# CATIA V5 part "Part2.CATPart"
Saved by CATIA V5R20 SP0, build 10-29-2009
Part number: Part2
Bounding box of the stored display mesh (mm): x -1.857 to 1.857, y -0.35 to 0.35, z -1.857 to 1.857
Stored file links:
  C:\Users\scupi\Desktop\Product\Part2.CATPart
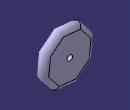
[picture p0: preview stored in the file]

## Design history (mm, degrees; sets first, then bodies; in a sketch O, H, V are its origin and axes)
Body1 (main body)
  Sketch1 on yz-plane, origin (0, 0, 0), H (0, 1, 0), V (0, 0, 1)
    line L1 (-0.35, 0.2) -> (0.35, 0.2)
    line L2 (0.35, 0.2) -> (0.35, 1.5854)
    line L3 (-0.35, 1.5854) -> (-0.35, 0.2)
    point P3 (0.35, 1.5854)
    arc A1 centre (0, 1.5854) radius 0.35 from (0.35, 1.5854) to (-0.35, 1.5854) ccw
    axis line L4 (1.3992, 0) -> (-1.3562, 0)
    point P6 (1.3992, 0)
    distance L2 L3 = 0.7
    distance L3 V = 0.35
    radius A1 = 0.35
    distance L1 H = 0.2
    distance P3 L4 = 1.5854
    horizontal: L1 H, L4 H
    vertical: L2 V, L3 V
    tangency: A1 L2
    coincidence: P6 H
  Shaft1: profile Sketch1, axis Sketch1.L4, angle 360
